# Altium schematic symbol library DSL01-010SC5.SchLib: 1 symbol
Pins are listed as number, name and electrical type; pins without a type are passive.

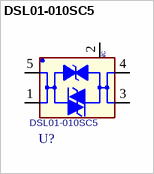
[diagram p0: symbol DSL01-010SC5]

## DSL01-010SC5
designator U?
footprint ST_SOT23-5L
pins: 1, 2, 3, 4, 5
